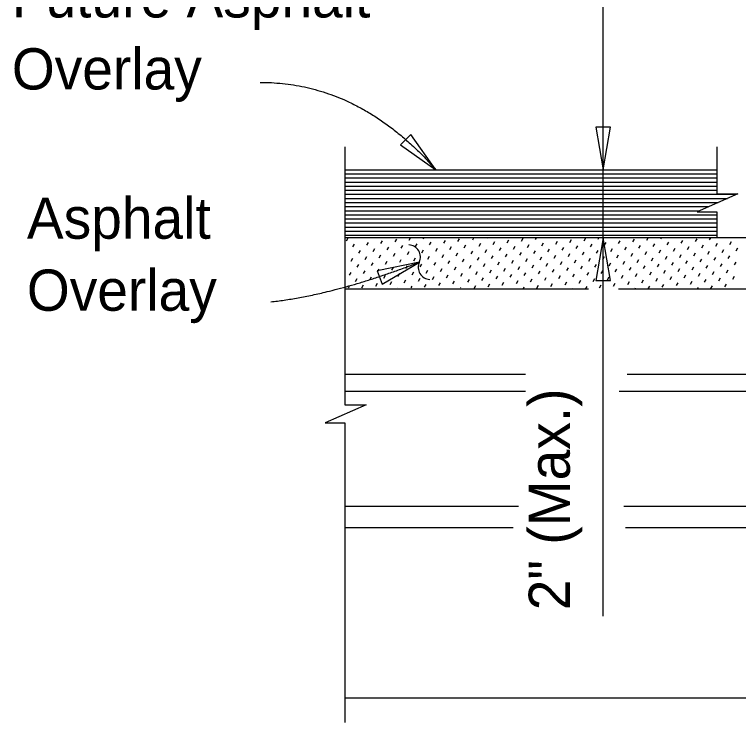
# Model space of a CAD drawing. Extents: x 130539.2 to 130573.7, y 88651.8 to 88671.1.
# Drawn here: x 130551.337 to 130553.108, y 88663.114 to 88664.844 of the extents above; entities that cross this region are included whole.
import ezdxf

# ---------------------------------------------------------------- set-up
doc = ezdxf.new("R2010")
doc.units = 0
for name, color, linetype in [('Dimension', 7, 'Continuous'), ('Miscellaneous', 7, 'Continuous'), ('Rebar_h', 7, 'Continuous'), ('TextStructures', 7, 'Continuous'), ('TrafBarrierConc', 7, 'Continuous')]:
    doc.layers.add(name, color=color, linetype=linetype)

msp = doc.modelspace()

# ---------------------------------------------------------------- linework, layer by layer
at = {"layer": 'Dimension'}
msp.add_line((130552.777, 88663.3733), (130552.777, 88666.9647), dxfattribs=at)
for points in [[(130552.777, 88664.4647), (130552.7946, 88664.5688), (130552.7593, 88664.5688)], [(130552.3676, 88664.4647), (130552.3065, 88664.5508), (130552.2815, 88664.5259)], [(130552.777, 88664.2981), (130552.7593, 88664.1939), (130552.7946, 88664.1939)], [(130552.3274, 88664.2387), (130552.2239, 88664.2179), (130552.2365, 88664.185)], [(130552.3274, 88664.2387), (130552.2239, 88664.2179), (130552.2365, 88664.185)]]:
    msp.add_lwpolyline(points, close=True, dxfattribs=at)
for points in [[(130552.1453, 88664.5209), (130552.1453, 88663.8901), (130552.197, 88663.8901), (130552.097, 88663.8459), (130552.1453, 88663.8459), (130552.1453, 88663.1138)], [(130553.0548, 88664.5209), (130553.0548, 88664.4061), (130553.1065, 88664.4061), (130553.0065, 88664.362), (130553.0548, 88664.362), (130553.0548, 88664.2981)]]:
    msp.add_lwpolyline(points, dxfattribs=at)
for centre, start, end in [((130552.3002, 88664.2515), 335.1447, 86.8719), ((130552.3002, 88664.2515), 335.1447, 86.8719), ((130552.3543, 88664.2265), 155.1447, 266.8719), ((130552.3543, 88664.2265), 155.1447, 266.8719)]:
    msp.add_arc(centre, 0.0298, start, end, dxfattribs=at)
for points in [[(130551.9378, 88664.6783), (130552.1799, 88664.6783), (130552.3676, 88664.4647)], [(130551.9642, 88664.1419), (130552.1199, 88664.1592), (130552.3274, 88664.2387)]]:
    msp.add_open_spline(points, degree=2, dxfattribs=at)
at = {"layer": 'Miscellaneous'}
for p, q in [((130552.1453, 88664.4647), (130553.0548, 88664.4647)), ((130552.1453, 88664.4547), (130553.0548, 88664.4547)), ((130552.1453, 88664.4447), (130553.0548, 88664.4447)), ((130552.1453, 88664.4347), (130553.0548, 88664.4347)), ((130552.1453, 88664.4247), (130553.0548, 88664.4247)), ((130552.1453, 88664.4147), (130553.0548, 88664.4147)), ((130552.1453, 88664.4047), (130553.1033, 88664.4047)), ((130552.1453, 88664.3947), (130553.0806, 88664.3947)), ((130552.1453, 88664.3847), (130553.058, 88664.3847)), ((130552.1453, 88664.3747), (130553.0353, 88664.3747)), ((130552.1453, 88664.3647), (130553.0127, 88664.3647)), ((130552.1453, 88664.3547), (130553.0548, 88664.3547)), ((130552.1453, 88664.3447), (130553.0548, 88664.3447)), ((130552.1453, 88664.3347), (130553.0548, 88664.3347)), ((130552.1453, 88664.3247), (130553.0548, 88664.3247)), ((130552.1453, 88664.3147), (130553.0548, 88664.3147)), ((130552.1453, 88664.3047), (130553.0548, 88664.3047)), ((130554.0785, 88664.2981), (130552.1453, 88664.2981)), ((130552.1491, 88664.2913), (130552.1531, 88664.2983)), ((130552.1643, 88664.2761), (130552.1684, 88664.2831)), ((130552.1989, 88664.2801), (130552.2029, 88664.2871)), ((130552.2334, 88664.2842), (130552.2375, 88664.2912)), ((130552.268, 88664.2882), (130552.272, 88664.2952)), ((130552.3025, 88664.2923), (130552.3058, 88664.2981)), ((130552.3178, 88664.277), (130552.3218, 88664.284)), ((130552.3371, 88664.2963), (130552.338, 88664.2981)), ((130552.3523, 88664.2811), (130552.3564, 88664.2881)), ((130552.3869, 88664.2852), (130552.3909, 88664.2921)), ((130552.4214, 88664.2892), (130552.4254, 88664.2962)), ((130552.458, 88664.2934), (130552.4606, 88664.2981)), ((130552.4732, 88664.2782), (130552.4773, 88664.2852)), ((130552.4925, 88664.2975), (130552.4928, 88664.2981)), ((130552.5078, 88664.2822), (130552.5118, 88664.2892)), ((130552.5423, 88664.2863), (130552.5464, 88664.2933)), ((130552.5768, 88664.2903), (130552.5809, 88664.2973)), ((130552.5921, 88664.2751), (130552.5961, 88664.2821)), ((130552.6114, 88664.2944), (130552.6135, 88664.2981)), ((130552.6266, 88664.2791), (130552.6307, 88664.2861)), ((130552.6612, 88664.2832), (130552.6652, 88664.2902)), ((130552.6957, 88664.2872), (130552.6998, 88664.2942)), ((130552.7303, 88664.2913), (130552.7342, 88664.2981)), ((130552.7455, 88664.276), (130552.7496, 88664.283)), ((130552.7648, 88664.2953), (130552.7664, 88664.2981)), ((130552.7801, 88664.2801), (130552.7841, 88664.2871)), ((130552.8146, 88664.2842), (130552.8187, 88664.2911)), ((130552.8492, 88664.2882), (130552.8532, 88664.2952)), ((130552.8837, 88664.2923), (130552.8871, 88664.2981)), ((130552.899, 88664.277), (130552.903, 88664.284)), ((130552.9182, 88664.2963), (130552.9193, 88664.2981)), ((130552.9335, 88664.2811), (130552.9375, 88664.2881)), ((130552.968, 88664.2851), (130552.9721, 88664.2921)), ((130553.0026, 88664.2892), (130553.0066, 88664.2962)), ((130553.0371, 88664.2932), (130553.0399, 88664.2981)), ((130553.0524, 88664.278), (130553.0564, 88664.285)), ((130553.0717, 88664.2973), (130553.0721, 88664.2981)), ((130553.0869, 88664.282), (130553.091, 88664.289)), ((130552.1796, 88664.2608), (130552.1836, 88664.2678)), ((130552.2141, 88664.2649), (130552.2182, 88664.2719)), ((130552.2487, 88664.2689), (130552.2527, 88664.2759)), ((130552.2832, 88664.273), (130552.2873, 88664.28)), ((130552.2985, 88664.2578), (130552.3025, 88664.2647)), ((130552.333, 88664.2618), (130552.3371, 88664.2688)), ((130552.3676, 88664.2659), (130552.3716, 88664.2729)), ((130552.4021, 88664.2699), (130552.4062, 88664.2769)), ((130552.4366, 88664.274), (130552.4407, 88664.281)), ((130552.4539, 88664.2589), (130552.458, 88664.2659)), ((130552.4885, 88664.2629), (130552.4925, 88664.2699)), ((130552.523, 88664.267), (130552.5271, 88664.274)), ((130552.5576, 88664.271), (130552.5616, 88664.278)), ((130552.6073, 88664.2598), (130552.6114, 88664.2668)), ((130552.6419, 88664.2639), (130552.6459, 88664.2709)), ((130552.6764, 88664.2679), (130552.6805, 88664.2749)), ((130552.711, 88664.272), (130552.715, 88664.279)), ((130552.7608, 88664.2608), (130552.7648, 88664.2678)), ((130552.7953, 88664.2649), (130552.7994, 88664.2719)), ((130552.8299, 88664.2689), (130552.8339, 88664.2759)), ((130552.8644, 88664.273), (130552.8685, 88664.28)), ((130552.8797, 88664.2577), (130552.8837, 88664.2647)), ((130552.9142, 88664.2618), (130552.9182, 88664.2688)), ((130552.9487, 88664.2658), (130552.9528, 88664.2728)), ((130552.9833, 88664.2699), (130552.9873, 88664.2769)), ((130553.0178, 88664.2739), (130553.0219, 88664.2809)), ((130553.0331, 88664.2587), (130553.0371, 88664.2657)), ((130553.0676, 88664.2627), (130553.0717, 88664.2697)), ((130553.1022, 88664.2668), (130553.1062, 88664.2738)), ((130552.1603, 88664.2415), (130552.1643, 88664.2485)), ((130552.1948, 88664.2456), (130552.1989, 88664.2526)), ((130552.2294, 88664.2496), (130552.2334, 88664.2566)), ((130552.2639, 88664.2537), (130552.268, 88664.2607)), ((130552.3137, 88664.2425), (130552.3178, 88664.2495)), ((130552.3483, 88664.2466), (130552.3523, 88664.2536)), ((130552.3828, 88664.2506), (130552.3869, 88664.2576)), ((130552.4173, 88664.2547), (130552.4214, 88664.2617)), ((130552.4692, 88664.2436), (130552.4732, 88664.2506)), ((130552.5037, 88664.2477), (130552.5078, 88664.2547)), ((130552.5383, 88664.2517), (130552.5423, 88664.2587)), ((130552.5728, 88664.2558), (130552.5768, 88664.2628)), ((130552.588, 88664.2405), (130552.5921, 88664.2475)), ((130552.6226, 88664.2446), (130552.6266, 88664.2516)), ((130552.6571, 88664.2486), (130552.6612, 88664.2556)), ((130552.6917, 88664.2527), (130552.6957, 88664.2597)), ((130552.7262, 88664.2568), (130552.7303, 88664.2637)), ((130552.7415, 88664.2415), (130552.7455, 88664.2485)), ((130552.776, 88664.2456), (130552.7801, 88664.2526)), ((130552.8106, 88664.2496), (130552.8146, 88664.2566)), ((130552.8451, 88664.2537), (130552.8492, 88664.2607)), ((130552.8949, 88664.2425), (130552.899, 88664.2495)), ((130552.9294, 88664.2465), (130552.9335, 88664.2535)), ((130552.964, 88664.2506), (130552.968, 88664.2576)), ((130552.9985, 88664.2546), (130553.0026, 88664.2616)), ((130553.0483, 88664.2434), (130553.0524, 88664.2504)), ((130553.0829, 88664.2475), (130553.0869, 88664.2545)), ((130552.1755, 88664.2263), (130552.1796, 88664.2333)), ((130552.2101, 88664.2304), (130552.2141, 88664.2373)), ((130552.2446, 88664.2344), (130552.2487, 88664.2414)), ((130552.2792, 88664.2385), (130552.2832, 88664.2455)), ((130552.2944, 88664.2232), (130552.2985, 88664.2302)), ((130552.329, 88664.2273), (130552.333, 88664.2343)), ((130552.3635, 88664.2313), (130552.3676, 88664.2383)), ((130552.398, 88664.2354), (130552.4021, 88664.2424)), ((130552.4326, 88664.2394), (130552.4366, 88664.2464)), ((130552.4499, 88664.2243), (130552.4539, 88664.2313)), ((130552.4844, 88664.2284), (130552.4885, 88664.2354)), ((130552.519, 88664.2324), (130552.523, 88664.2394)), ((130552.5535, 88664.2365), (130552.5576, 88664.2435)), ((130552.6033, 88664.2253), (130552.6073, 88664.2323)), ((130552.6378, 88664.2294), (130552.6419, 88664.2363)), ((130552.6724, 88664.2334), (130552.6764, 88664.2404)), ((130552.7069, 88664.2375), (130552.711, 88664.2445)), ((130552.7222, 88664.2222), (130552.7262, 88664.2292)), ((130552.7567, 88664.2263), (130552.7608, 88664.2333)), ((130552.7913, 88664.2303), (130552.7953, 88664.2373)), ((130552.8258, 88664.2344), (130552.8299, 88664.2414)), ((130552.8604, 88664.2384), (130552.8644, 88664.2454)), ((130552.8756, 88664.2232), (130552.8797, 88664.2302)), ((130552.9101, 88664.2272), (130552.9142, 88664.2342)), ((130552.9447, 88664.2313), (130552.9487, 88664.2383)), ((130552.9792, 88664.2353), (130552.9833, 88664.2423)), ((130553.0138, 88664.2394), (130553.0178, 88664.2464)), ((130553.029, 88664.2241), (130553.0331, 88664.2311)), ((130553.0636, 88664.2282), (130553.0676, 88664.2352)), ((130553.0981, 88664.2322), (130553.1022, 88664.2392)), ((130552.1562, 88664.207), (130552.1603, 88664.214)), ((130552.1908, 88664.2111), (130552.1948, 88664.218)), ((130552.2253, 88664.2151), (130552.2294, 88664.2221)), ((130552.2599, 88664.2192), (130552.2639, 88664.2262)), ((130552.3097, 88664.208), (130552.3137, 88664.215)), ((130552.3442, 88664.212), (130552.3483, 88664.219)), ((130552.3788, 88664.2161), (130552.3828, 88664.2231)), ((130552.4133, 88664.2201), (130552.4173, 88664.2271)), ((130552.4285, 88664.2049), (130552.4326, 88664.2119)), ((130552.4651, 88664.2091), (130552.4692, 88664.2161)), ((130552.4997, 88664.2131), (130552.5037, 88664.2201)), ((130552.5342, 88664.2172), (130552.5383, 88664.2242)), ((130552.5687, 88664.2212), (130552.5728, 88664.2282)), ((130552.584, 88664.206), (130552.588, 88664.213)), ((130552.6185, 88664.2101), (130552.6226, 88664.2171)), ((130552.6531, 88664.2141), (130552.6571, 88664.2211)), ((130552.6876, 88664.2182), (130552.6917, 88664.2252)), ((130552.7374, 88664.207), (130552.7415, 88664.214)), ((130552.772, 88664.211), (130552.776, 88664.218)), ((130552.8065, 88664.2151), (130552.8106, 88664.2221)), ((130552.8411, 88664.2191), (130552.8451, 88664.2261)), ((130552.8908, 88664.2079), (130552.8949, 88664.2149)), ((130552.9254, 88664.212), (130552.9294, 88664.219)), ((130552.9599, 88664.216), (130552.964, 88664.223)), ((130552.9945, 88664.2201), (130552.9985, 88664.2271)), ((130553.0097, 88664.2048), (130553.0138, 88664.2118)), ((130553.0443, 88664.2089), (130553.0483, 88664.2159)), ((130553.0788, 88664.2129), (130553.0829, 88664.2199)), ((130552.1715, 88664.1918), (130552.1755, 88664.1988)), ((130552.206, 88664.1958), (130552.2101, 88664.2028)), ((130552.2406, 88664.1999), (130552.2446, 88664.2069)), ((130552.2751, 88664.2039), (130552.2792, 88664.2109)), ((130552.2904, 88664.1887), (130552.2944, 88664.1957)), ((130552.3249, 88664.1927), (130552.329, 88664.1997)), ((130552.3595, 88664.1968), (130552.3635, 88664.2038)), ((130552.394, 88664.2008), (130552.398, 88664.2078)), ((130552.4458, 88664.1898), (130552.4499, 88664.1968)), ((130552.4804, 88664.1938), (130552.4844, 88664.2008)), ((130552.5149, 88664.1979), (130552.519, 88664.2049)), ((130552.5494, 88664.202), (130552.5535, 88664.2089)), ((130552.5647, 88664.1867), (130552.5687, 88664.1937)), ((130552.5992, 88664.1908), (130552.6033, 88664.1978)), ((130552.6338, 88664.1948), (130552.6378, 88664.2018)), ((130552.6683, 88664.1989), (130552.6724, 88664.2059)), ((130552.7029, 88664.2029), (130552.7069, 88664.2099)), ((130552.7181, 88664.1877), (130552.7222, 88664.1947)), ((130552.7527, 88664.1917), (130552.7567, 88664.1987)), ((130552.7872, 88664.1958), (130552.7913, 88664.2028)), ((130552.8218, 88664.1998), (130552.8258, 88664.2068)), ((130552.8563, 88664.2039), (130552.8604, 88664.2109)), ((130552.8716, 88664.1886), (130552.8756, 88664.1956)), ((130552.9061, 88664.1927), (130552.9101, 88664.1997)), ((130552.9406, 88664.1967), (130552.9447, 88664.2037)), ((130552.9752, 88664.2008), (130552.9792, 88664.2078)), ((130553.025, 88664.1896), (130553.029, 88664.1966)), ((130553.0595, 88664.1936), (130553.0636, 88664.2006)), ((130553.0941, 88664.1977), (130553.0981, 88664.2047)), ((130552.1543, 88664.1762), (130552.1562, 88664.1795)), ((130552.1867, 88664.1765), (130552.1908, 88664.1835)), ((130552.2213, 88664.1806), (130552.2253, 88664.1876)), ((130552.2558, 88664.1846), (130552.2599, 88664.1916)), ((130552.275, 88664.1762), (130552.2751, 88664.1764)), ((130552.3072, 88664.1762), (130552.3097, 88664.1804)), ((130552.3402, 88664.1775), (130552.3442, 88664.1845)), ((130552.3747, 88664.1815), (130552.3788, 88664.1885)), ((130552.4092, 88664.1856), (130552.4133, 88664.1926)), ((130552.4279, 88664.1762), (130552.4285, 88664.1773)), ((130552.4611, 88664.1746), (130552.4651, 88664.1815)), ((130552.4956, 88664.1786), (130552.4997, 88664.1856)), ((130552.5302, 88664.1827), (130552.5342, 88664.1896)), ((130552.5809, 88664.1731), (130552.584, 88664.1785)), ((130552.6145, 88664.1755), (130552.6185, 88664.1825)), ((130552.649, 88664.1796), (130552.6531, 88664.1866)), ((130552.6836, 88664.1836), (130552.6876, 88664.1906)), ((130552.7337, 88664.1731), (130552.7374, 88664.1794)), ((130552.7679, 88664.1765), (130552.772, 88664.1835)), ((130552.8025, 88664.1805), (130552.8065, 88664.1875)), ((130552.837, 88664.1846), (130552.8411, 88664.1916)), ((130552.8544, 88664.1731), (130552.8563, 88664.1763)), ((130552.8868, 88664.1734), (130552.8908, 88664.1804)), ((130552.9213, 88664.1774), (130552.9254, 88664.1844)), ((130552.9559, 88664.1815), (130552.9599, 88664.1885)), ((130552.9904, 88664.1855), (130552.9945, 88664.1925)), ((130553.0073, 88664.1731), (130553.0097, 88664.1773)), ((130553.0402, 88664.1743), (130553.0443, 88664.1813)), ((130553.0748, 88664.1784), (130553.0788, 88664.1854)), ((130552.5487, 88664.1731), (130552.5494, 88664.1744)), ((130552.7015, 88664.1731), (130552.7029, 88664.1754)), ((130552.9751, 88664.1731), (130552.9752, 88664.1732))]:
    msp.add_line(p, q, dxfattribs=at)
at = {"layer": 'Rebar_h'}
for p, q in [((130552.5871, 88663.9647), (130552.1453, 88663.9647)), ((130554.3471, 88663.9647), (130552.8358, 88663.9647)), ((130552.5871, 88663.923), (130552.1453, 88663.923)), ((130554.3471, 88663.923), (130552.8162, 88663.923)), ((130552.5697, 88663.6418), (130552.1453, 88663.6418)), ((130555.1221, 88663.6418), (130552.8271, 88663.6418)), ((130552.5566, 88663.5897), (130552.1453, 88663.5897)), ((130555.1221, 88663.5897), (130552.8314, 88663.5897))]:
    msp.add_line(p, q, dxfattribs=at)
at = {"layer": 'TrafBarrierConc'}
for p, q in [((130552.7408, 88664.1731), (130552.1453, 88664.1731)), ((130554.0785, 88664.1731), (130552.8142, 88664.1731)), ((130555.2887, 88663.1731), (130552.1453, 88663.1731))]:
    msp.add_line(p, q, dxfattribs=at)

# ---------------------------------------------------------------- texts
at = {"layer": 'Dimension'}
for s, p in [('Future Asphalt ', (130551.3308, 88664.8369)), ('Overlay', (130551.3308, 88664.6609)), ('Asphalt ', (130551.3675, 88664.2961)), ('Overlay', (130551.3675, 88664.1201))]:
    msp.add_text(s, height=0.1008, dxfattribs=at).set_placement(p)
at = {"layer": 'TextStructures'}
msp.add_text('2" (Max.)', height=0.1008, rotation=90, dxfattribs=at).set_placement((130552.6955, 88663.3881))

doc.saveas('drawing.dxf')
